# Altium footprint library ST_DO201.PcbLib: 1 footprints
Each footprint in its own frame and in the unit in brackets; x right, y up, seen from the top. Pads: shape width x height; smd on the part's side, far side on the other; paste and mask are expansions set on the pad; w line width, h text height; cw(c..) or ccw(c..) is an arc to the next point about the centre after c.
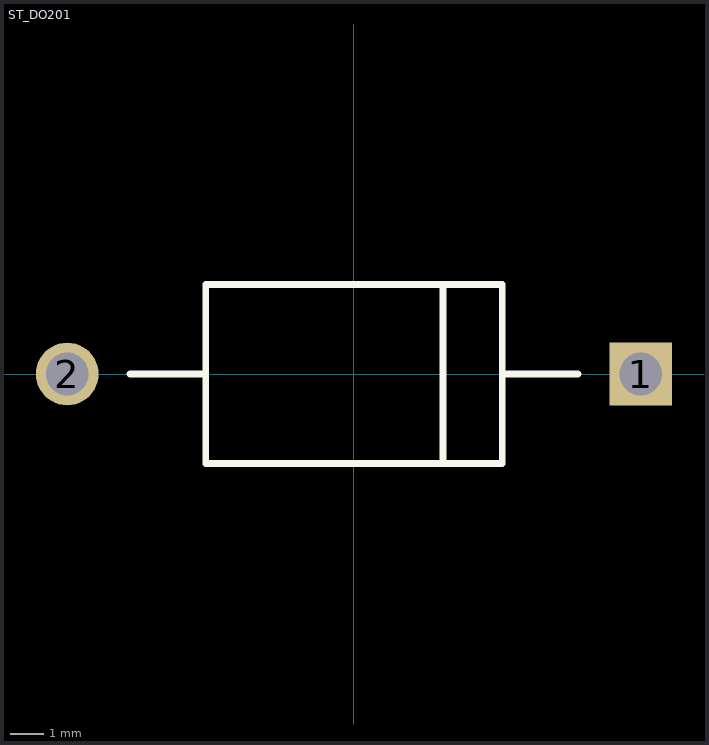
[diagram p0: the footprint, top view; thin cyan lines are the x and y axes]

## ST_DO201 [mm]
pads (2):
  rect 1.86x1.86 hole 1.26: 1(8.5,0)
  round 1.86 hole 1.26: 2(-8.5,0)
Top Overlay:
  lines w0.2: -6.64,0 -4.395,0 ; 2.638,-2.65 2.638,2.65 ; 4.395,0 6.64,0 ; -4.395,0 -4.395,-2.65 4.395,-2.65 4.395,2.65 -4.395,2.65 -4.395,0
3D body "ST_DO201.step": height 5.3, standoff 0, extent -4.75,-2.65 4.75,2.65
